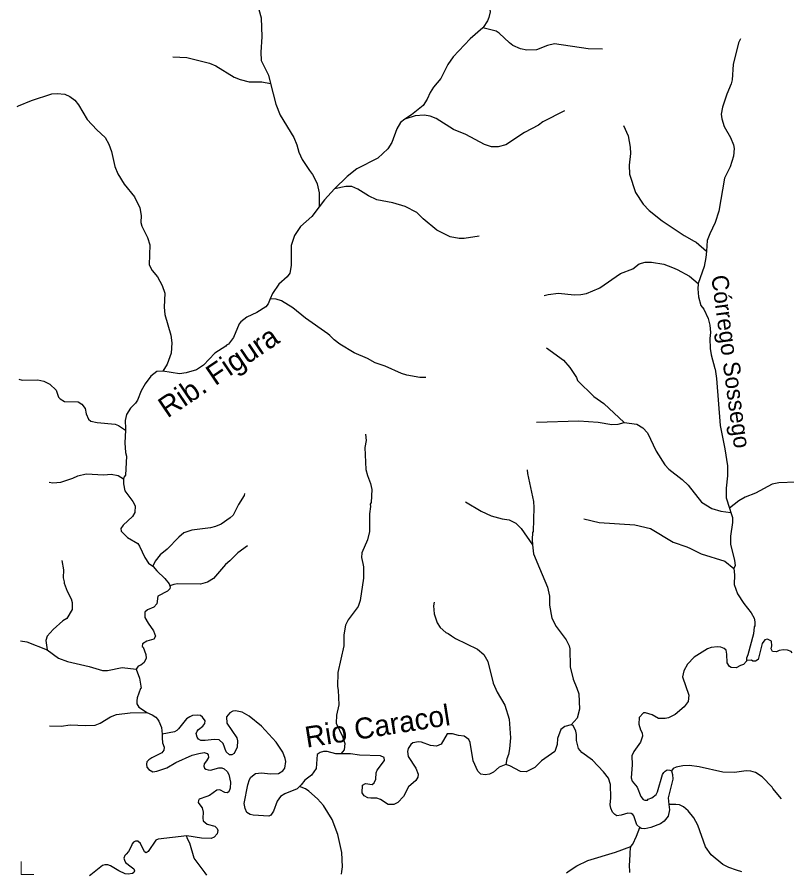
# Model space of a CAD drawing. Extents: x 280.4 to 335.6, y 8893.9 to 8949.5.
# Drawn here: x 280.72 to 288.06, y 8893.92 to 8902.11 of the extents above; entities that cross this region are included whole.
import ezdxf
from ezdxf.enums import TextEntityAlignment as Align

# ---------------------------------------------------------------- set-up
doc = ezdxf.new("R2010")
doc.units = 0
doc.header["$LTSCALE"] = 0.064
doc.linetypes.add('LONG_DASHED', pattern=[7.5, 6, -1.5])
doc.layers.add('61', color=7, linetype='Continuous')
for name, color, linetype, lineweight in [('63', 7, 'Continuous', 13), ('7', 7, 'Continuous', 25), ('9', 7, 'LONG_DASHED', 25)]:
    doc.layers.add(name, color=color, linetype=linetype, lineweight=lineweight)

msp = doc.modelspace()

# ---------------------------------------------------------------- linework, layer by layer
at = {"layer": '63'}
msp.add_lwpolyline([(280.7592, 8894.0583), (280.7592, 8893.9351), (280.8806, 8893.9351)], dxfattribs=at)
at = {"layer": '7'}
msp.add_line((287.5146, 8897.4319), (287.5285, 8897.3884), dxfattribs=at)
for points in [[(285.4001, 8903.403), (285.3942, 8903.3035), (285.3886, 8903.2783), (285.3837, 8903.2596), (285.3395, 8903.1456), (285.2786, 8902.9441), (285.2721, 8902.8349), (285.2848, 8902.7131), (285.2816, 8902.6123), (285.2745, 8902.6053), (285.2499, 8902.5123), (285.2237, 8902.4525), (285.2053, 8902.3693), (285.2336, 8902.1669), (285.2217, 8902.1113), (285.2081, 8902.0799), (285.1646, 8902.0151), (285.1635, 8902.0141)], [(282.7142, 8902.8866), (282.7191, 8902.8812), (282.8616, 8902.669), (282.9288, 8902.5283), (282.9689, 8902.4228), (283.0096, 8902.2445), (283.0488, 8902.1071), (283.0555, 8901.9278), (283.0444, 8901.78), (283.0492, 8901.7026), (283.1196, 8901.561), (283.1389, 8901.4832)], [(285.1635, 8902.0141), (285.0413, 8901.9082), (284.8791, 8901.735), (284.8296, 8901.6631), (284.7614, 8901.5309), (284.6938, 8901.4481), (284.6612, 8901.3953), (284.6327, 8901.3321), (284.5923, 8901.2723), (284.4833, 8901.1815), (284.418, 8901.1425)], [(286.3049, 8901.8106), (286.1668, 8901.8121), (285.8457, 8901.8592), (285.7795, 8901.8454), (285.6734, 8901.8018), (285.5824, 8901.7989), (285.5228, 8901.8139), (285.4491, 8901.8451), (285.4163, 8901.8684), (285.3198, 8901.9635), (285.2912, 8901.9807), (285.1635, 8902.0141)], [(287.6204, 8901.908), (287.6008, 8901.8695), (287.5493, 8901.6634), (287.5399, 8901.5176), (287.5319, 8901.4792), (287.4901, 8901.3802), (287.4487, 8901.2562), (287.4376, 8901.1881), (287.4424, 8901.1449), (287.4647, 8901.0725), (287.5254, 8900.9667), (287.5524, 8900.8971), (287.5589, 8900.8612), (287.5525, 8900.7901), (287.5225, 8900.6861), (287.4677, 8900.579), (287.4133, 8900.2624), (287.3796, 8900.1568), (287.3275, 8900.0491), (287.304, 8899.9846), (287.2957, 8899.8825)], [(282.2074, 8901.7356), (282.3408, 8901.7299), (282.5554, 8901.6767), (282.6179, 8901.6492), (282.7915, 8901.5433), (282.8476, 8901.5186), (282.9347, 8901.4994), (283.0563, 8901.4992), (283.1389, 8901.4832)], [(283.1389, 8901.4832), (283.1883, 8901.2835), (283.2302, 8901.1807), (283.3593, 8900.9667), (283.3881, 8900.8964), (283.4077, 8900.8253), (283.4401, 8900.7572), (283.5083, 8900.6504), (283.5395, 8900.615), (283.5696, 8900.5533), (283.5832, 8900.5253), (283.6024, 8900.439), (283.6014, 8900.3039)], [(280.7217, 8901.2629), (280.7357, 8901.2688), (280.8587, 8901.3203), (281.0536, 8901.383), (281.1033, 8901.3874), (281.1777, 8901.3791), (281.2253, 8901.357), (281.273, 8901.3225), (281.3073, 8901.2774), (281.3896, 8901.139), (281.4813, 8901.0409), (281.562, 8900.9676), (281.5951, 8900.9035), (281.6225, 8900.8324), (281.6532, 8900.691), (281.6805, 8900.6207), (281.7407, 8900.5215), (281.842, 8900.4), (281.8906, 8900.2966), (281.904, 8900.224), (281.9025, 8900.1551), (281.9103, 8900.1199), (281.9655, 8900.012), (281.9855, 8899.9432), (281.981, 8899.7521), (282.0078, 8899.6978), (282.0596, 8899.636), (282.1058, 8899.5554), (282.131, 8899.4801), (282.1248, 8899.3468), (282.1307, 8899.2777), (282.1886, 8899.0803), (282.1982, 8899.0085), (282.1902, 8898.9102), (282.1511, 8898.803), (282.1104, 8898.738)], [(285.9413, 8901.2216), (285.7354, 8901.1178), (285.6953, 8901.085), (285.5592, 8901.0136), (285.3824, 8900.8965), (285.3098, 8900.8773), (285.2471, 8900.8788), (285.18, 8900.901), (285.0001, 8900.9957), (284.8819, 8901.0436), (284.7194, 8901.1486), (284.6618, 8901.1696), (284.6036, 8901.1794), (284.5172, 8901.1745), (284.418, 8901.1425)], [(284.418, 8901.1425), (284.3778, 8901.1085), (284.3433, 8901.0506), (284.2957, 8900.9205), (284.2576, 8900.8591), (284.1612, 8900.7689), (283.9625, 8900.6669), (283.8701, 8900.5962), (283.7483, 8900.4786), (283.7478, 8900.478)], [(286.5054, 8901.0797), (286.5483, 8900.982), (286.5696, 8900.873), (286.5707, 8900.8133), (286.558, 8900.7027), (286.5612, 8900.6172), (286.6194, 8900.4435), (286.6914, 8900.3323), (286.7489, 8900.269), (286.8723, 8900.172), (287.0818, 8900.0317), (287.1798, 8899.9784), (287.1982, 8899.9684), (287.2957, 8899.8825)], [(283.7478, 8900.478), (283.6536, 8900.3718), (283.6014, 8900.3039)], [(285.1265, 8900.0239), (284.9842, 8900.0025), (284.938, 8900.0026), (284.8523, 8900.0177), (284.7251, 8900.0812), (284.5935, 8900.1916), (284.5348, 8900.2503), (284.4218, 8900.3075), (284.3036, 8900.3428), (284.1508, 8900.3714), (284.0727, 8900.4103), (283.971, 8900.4738), (283.9134, 8900.4979), (283.8552, 8900.4997), (283.7478, 8900.478)], [(283.6014, 8900.3039), (283.5316, 8900.213), (283.424, 8900.1178), (283.3661, 8900.0303), (283.3344, 8899.9365), (283.3353, 8899.7449), (283.321, 8899.6721), (283.2969, 8899.6378), (283.2174, 8899.5677), (283.1582, 8899.4769), (283.1361, 8899.4265)], [(287.2957, 8899.8825), (287.2907, 8899.8216), (287.2743, 8899.7354), (287.2172, 8899.5736)], [(285.7466, 8899.4581), (285.7853, 8899.4702), (285.8849, 8899.4825), (286.0351, 8899.4667), (286.0981, 8899.4676), (286.1516, 8899.4795), (286.2726, 8899.5295), (286.2802, 8899.5326), (286.4759, 8899.6701), (286.5933, 8899.7146), (286.6555, 8899.7609), (286.7121, 8899.7769), (286.7706, 8899.7768), (286.8905, 8899.7576), (286.9717, 8899.7263), (287.0169, 8899.7088), (287.135, 8899.6448), (287.2172, 8899.5736)], [(287.2172, 8899.5736), (287.2159, 8899.57), (287.2124, 8899.5235), (287.2183, 8899.4467), (287.2418, 8899.3628), (287.2704, 8899.33), (287.311, 8899.2395), (287.3271, 8899.1756), (287.3352, 8899.1067), (287.3288, 8899.0493), (287.3306, 8898.9533), (287.3412, 8898.8925), (287.3767, 8898.763), (287.3778, 8898.7564), (287.3926, 8898.667), (287.4279, 8898.22), (287.4725, 8897.996), (287.495, 8897.8347), (287.495, 8897.7394), (287.4823, 8897.6218), (287.4839, 8897.5284), (287.5146, 8897.4319)], [(283.1361, 8899.4265), (283.1154, 8899.3792), (283.0929, 8899.3505), (283.0082, 8899.2975), (282.9109, 8899.2518), (282.8562, 8899.2092), (282.8404, 8899.1879), (282.7835, 8899.0573), (282.7381, 8898.9946), (282.7167, 8898.9865), (282.7109, 8898.9755), (282.6075, 8898.9102), (282.4994, 8898.7956), (282.4313, 8898.7518), (282.3326, 8898.7215), (282.2703, 8898.7136), (282.1104, 8898.738)], [(284.6181, 8898.6768), (284.5625, 8898.6783), (284.4373, 8898.6991), (284.3887, 8898.7138), (284.2299, 8898.7866), (284.1347, 8898.8184), (284.0626, 8898.8584), (283.936, 8898.9112), (283.7992, 8898.9952), (283.7461, 8899.0354), (283.7028, 8899.0773), (283.6856, 8899.094), (283.4727, 8899.2441), (283.3518, 8899.3431), (283.2442, 8899.409), (283.1921, 8899.4248), (283.1361, 8899.4265)], [(285.7712, 8898.9599), (285.9314, 8898.8425), (285.9917, 8898.7725), (286.0557, 8898.6766), (286.0643, 8898.6488), (286.2221, 8898.4945), (286.3185, 8898.4281), (286.5102, 8898.2477)], [(282.1104, 8898.738), (282.055, 8898.7334), (281.9956, 8898.6906), (281.9419, 8898.6173), (281.9044, 8898.5494), (281.87, 8898.4617), (281.8507, 8898.433)], [(280.7373, 8898.6615), (280.7684, 8898.6515), (280.9182, 8898.6558), (280.9771, 8898.6427), (281.034, 8898.6126), (281.0942, 8898.5554), (281.1157, 8898.4906), (281.1315, 8898.4732), (281.1724, 8898.4496), (281.3036, 8898.4464), (281.3394, 8898.4222), (281.3698, 8898.38), (281.3799, 8898.3305), (281.4021, 8898.2794), (281.4238, 8898.2613), (281.4835, 8898.2467), (281.657, 8898.2305), (281.6865, 8898.2207), (281.7543, 8898.1759)], [(281.8507, 8898.433), (281.8013, 8898.3849), (281.7636, 8898.3253), (281.7507, 8898.2679), (281.7552, 8898.1917), (281.7543, 8898.1759)], [(285.6761, 8898.2523), (286.0773, 8898.264), (286.2636, 8898.2512), (286.3923, 8898.2289), (286.453, 8898.2307), (286.5102, 8898.2477)], [(286.5102, 8898.2477), (286.6307, 8898.2305), (286.6905, 8898.197), (286.7339, 8898.1496), (286.8166, 8897.9736), (286.8986, 8897.8435), (286.9368, 8897.8027), (287.0642, 8897.7047), (287.1224, 8897.6499), (287.2477, 8897.488), (287.3473, 8897.4282), (287.3486, 8897.4274), (287.4343, 8897.4005), (287.5285, 8897.3884)], [(281.7543, 8898.1759), (281.7475, 8898.0546), (281.7539, 8897.9602), (281.7633, 8897.9274), (281.7536, 8897.7461), (281.7409, 8897.7305), (281.7349, 8897.7093)], [(284.0444, 8898.1367), (284.0489, 8898.0759), (284.0377, 8898.0091), (284.0471, 8897.8009), (284.0615, 8897.7435), (284.092, 8897.6653), (284.1046, 8897.6076), (284.0981, 8897.4855), (284.0892, 8897.4676), (284.0918, 8897.446), (284.0823, 8897.378), (284.0806, 8897.2092), (284.063, 8897.1286), (284.0083, 8897.0043), (284.0069, 8896.9605), (284.0179, 8896.904), (284.0246, 8896.8694), (284.0261, 8896.7639), (283.9941, 8896.5497), (283.9731, 8896.4915), (283.878, 8896.3646), (283.8535, 8896.3156), (283.836, 8896.2209), (283.8386, 8896.118), (283.7785, 8895.8626), (283.7753, 8895.7277), (283.7832, 8895.6939), (283.7911, 8895.5556), (283.7657, 8895.4557), (283.7625, 8895.3787), (283.8238, 8895.2526), (283.8454, 8895.1838), (283.8389, 8895.1248), (283.8073, 8895.0874)], [(288.541, 8898.1756), (288.4966, 8898.0414), (288.4129, 8897.8643), (288.3765, 8897.8128), (288.3176, 8897.7531), (288.2442, 8897.711), (288.1491, 8897.6791), (287.9876, 8897.6723), (287.923, 8897.6592), (287.7644, 8897.5751), (287.6662, 8897.5355), (287.6053, 8897.502), (287.5146, 8897.4319)], [(285.5854, 8897.7958), (285.5874, 8897.7628), (285.6446, 8897.4931), (285.6494, 8897.4363), (285.6432, 8897.2064), (285.6379, 8897.198), (285.6323, 8897.1315), (285.6368, 8897.0814)], [(281.0276, 8897.6784), (281.062, 8897.671), (281.139, 8897.6801), (281.2521, 8897.7157), (281.3016, 8897.7385), (281.3804, 8897.757), (281.5473, 8897.7491), (281.6177, 8897.7551), (281.6833, 8897.7409), (281.7349, 8897.7093)], [(281.7349, 8897.7093), (281.7348, 8897.6638), (281.7474, 8897.5965), (281.8256, 8897.4947), (281.8478, 8897.4516), (281.8447, 8897.3878), (281.8224, 8897.3524), (281.7331, 8897.2675), (281.7096, 8897.2357), (281.712, 8897.2117), (281.7724, 8897.1499), (281.873, 8897.0919), (281.8899, 8897.0686), (281.9377, 8896.9591), (281.9728, 8896.9052), (282.0147, 8896.8762)], [(282.8886, 8897.5713), (282.8863, 8897.5516), (282.8313, 8897.467), (282.7815, 8897.3647), (282.7526, 8897.3368), (282.6687, 8897.2777), (282.6147, 8897.254), (282.5646, 8897.2419), (282.3871, 8897.2197), (282.3106, 8897.1949), (282.2633, 8897.1551), (282.1524, 8897.0394), (282.0859, 8896.9857), (282.0384, 8896.9238), (282.0147, 8896.8762)], [(284.9973, 8897.4917), (285.1477, 8897.4003), (285.2427, 8897.357), (285.3481, 8897.3287), (285.4144, 8897.3183), (285.4762, 8897.2888), (285.5279, 8897.2357), (285.6368, 8897.0814)], [(287.5285, 8897.3884), (287.543, 8897.3428), (287.543, 8897.2923), (287.524, 8897.1644), (287.5239, 8897.0877), (287.5639, 8896.9319), (287.5684, 8896.883), (287.5562, 8896.8554)], [(286.1248, 8897.3293), (286.2739, 8897.2948), (286.6131, 8897.2726), (286.7626, 8897.2357), (286.9798, 8897.1072), (287.1096, 8897.0613), (287.1429, 8897.0448), (287.2459, 8896.9935), (287.4709, 8896.9246), (287.5562, 8896.8554)], [(282.9175, 8897.0713), (282.8247, 8897.0034), (282.7505, 8896.9276), (282.708, 8896.8929), (282.5934, 8896.7608), (282.5357, 8896.7257), (282.4694, 8896.7051), (282.2497, 8896.7083), (282.2151, 8896.7032), (282.1775, 8896.688)], [(285.6368, 8897.0814), (285.6447, 8896.9948), (285.7027, 8896.8593), (285.7803, 8896.6782), (285.7982, 8896.5912), (285.7983, 8896.5056), (285.8226, 8896.3803), (285.8611, 8896.3027), (285.9581, 8896.1753), (285.985, 8896.1185), (285.9917, 8896.0883), (285.995, 8895.9171), (286.0231, 8895.7984), (286.0608, 8895.7141), (286.0778, 8895.6588), (286.0845, 8895.5141), (286.0619, 8895.427), (286.0065, 8895.3629)], [(282.0147, 8896.8762), (282.0193, 8896.873), (282.0522, 8896.8331), (282.1295, 8896.7591), (282.1717, 8896.7085), (282.1775, 8896.688)], [(287.5562, 8896.8554), (287.5621, 8896.7957), (287.5609, 8896.7025), (287.5917, 8896.6126), (287.6513, 8896.5215), (287.7221, 8896.4319), (287.7497, 8896.3796), (287.7573, 8896.3473), (287.7573, 8896.3094), (287.751, 8896.299), (287.7444, 8896.2322), (287.6898, 8896.0308), (287.6765, 8895.9996), (287.6764, 8895.9703)], [(282.1775, 8896.688), (282.1801, 8896.6789), (282.1779, 8896.6602), (282.1554, 8896.6392), (282.0639, 8896.5904), (282.0544, 8896.5183), (282.0265, 8896.4865), (281.9649, 8896.4615), (281.9377, 8896.4368), (281.9394, 8896.3888), (281.9703, 8896.3337), (282.0224, 8896.2617), (282.0397, 8896.2106), (282.0248, 8896.18), (281.9592, 8896.1611), (281.9156, 8896.135), (281.914, 8896.1101), (281.9218, 8896.1035), (281.9485, 8896.0353), (281.9516, 8895.999), (281.9338, 8895.9576), (281.9012, 8895.9329), (281.877, 8895.9241), (281.8551, 8895.8945)], [(284.6974, 8896.5339), (284.6933, 8896.4995), (284.7002, 8896.4224), (284.7269, 8896.3353), (284.7545, 8896.2916), (284.8088, 8896.2441), (284.8316, 8896.2355), (284.8651, 8896.2119), (284.9011, 8896.1866), (285.1111, 8896.0854), (285.1732, 8896.0339), (285.211, 8895.9681), (285.2629, 8895.7625), (285.2996, 8895.6759), (285.3728, 8895.5516), (285.4126, 8895.418), (285.4256, 8895.2382), (285.4174, 8895.1344), (285.4068, 8895.0797), (285.3904, 8895.0375), (285.3838, 8894.9843)], [(288.1132, 8896.0501), (288.1045, 8896.063), (288.0677, 8896.0768), (288.0305, 8896.0797), (287.9877, 8896.0733), (287.9641, 8896.0587), (287.9245, 8896.0635), (287.9128, 8896.089), (287.9188, 8896.118), (287.9169, 8896.1608), (287.8773, 8896.1796), (287.8534, 8896.1738), (287.8286, 8896.1385), (287.7874, 8895.9854), (287.7644, 8895.9708), (287.7367, 8895.9722), (287.7246, 8895.9817), (287.6819, 8895.9764), (287.6764, 8895.9703)], [(287.6764, 8895.9703), (287.6492, 8895.9404), (287.6192, 8895.9309), (287.5807, 8895.9084), (287.5326, 8895.909), (287.5147, 8895.9209), (287.4921, 8895.9536), (287.4915, 8896.0383), (287.4822, 8896.0756), (287.4641, 8896.0912), (287.4337, 8896.1034), (287.4016, 8896.1066), (287.34, 8896.1005), (287.3057, 8896.0886), (287.1797, 8896.0074), (287.1161, 8895.9419), (287.0793, 8895.8779), (287.0684, 8895.8206), (287.1271, 8895.6469), (287.1214, 8895.5863), (287.0835, 8895.5351), (286.9961, 8895.4622), (286.9337, 8895.4308), (286.903, 8895.4228), (286.8369, 8895.4253), (286.7786, 8895.4573)], [(281.8551, 8895.8945), (281.8884, 8895.808), (281.9038, 8895.7125), (281.8977, 8895.7091), (281.8672, 8895.6213), (281.8625, 8895.5932), (281.8626, 8895.5653), (281.882, 8895.5327), (281.9559, 8895.4833), (281.9575, 8895.4826)], [(281.0308, 8895.3553), (281.1428, 8895.3518), (281.227, 8895.3646), (281.3742, 8895.3565), (281.4645, 8895.3612), (281.5126, 8895.3783), (281.6109, 8895.4411), (281.6687, 8895.4608), (281.8002, 8895.4764), (281.9575, 8895.4826)], [(281.9575, 8895.4826), (282.0096, 8895.4603), (282.0438, 8895.4374), (282.0614, 8895.4189), (282.074, 8895.3982), (282.099, 8895.3373), (282.1055, 8895.2733)], [(283.4141, 8894.7752), (283.3921, 8894.7543), (283.2731, 8894.7039), (283.2347, 8894.6783), (283.2024, 8894.6362), (283.1658, 8894.541), (283.1416, 8894.5012), (283.1228, 8894.4913), (282.9724, 8894.501), (282.9443, 8894.5088), (282.9134, 8894.5286), (282.8957, 8894.5642), (282.8881, 8894.6118), (282.9217, 8894.79), (282.9382, 8894.8432), (282.9515, 8894.8638), (282.9946, 8894.8977), (283.053, 8894.904), (283.1379, 8894.8944), (283.2134, 8894.8988), (283.2547, 8894.9243), (283.2744, 8894.9498), (283.2825, 8895.0143), (283.2775, 8895.0438), (283.2539, 8895.1032), (283.1914, 8895.1966), (283.0523, 8895.3517), (282.9349, 8895.4449), (282.866, 8895.4847), (282.8053, 8895.4972), (282.7773, 8895.494), (282.7495, 8895.4788), (282.7181, 8895.4383), (282.7198, 8895.3781), (282.8157, 8895.2408), (282.822, 8895.2094), (282.8188, 8895.1518), (282.7924, 8895.0899), (282.7676, 8895.077), (282.7456, 8895.0771), (282.7163, 8895.1045), (282.6858, 8895.1869), (282.6486, 8895.2206), (282.5997, 8895.2238), (282.5133, 8895.2127), (282.4732, 8895.2143), (282.4523, 8895.2262), (282.4393, 8895.2463), (282.4292, 8895.2804), (282.4376, 8895.302), (282.4499, 8895.3179), (282.4925, 8895.3518), (282.5128, 8895.3768), (282.5147, 8895.4013), (282.4908, 8895.436), (282.4701, 8895.4523), (282.4386, 8895.4572), (282.3942, 8895.4515), (282.37, 8895.4394), (282.3363, 8895.4219), (282.2593, 8895.3246), (282.2452, 8895.3083), (282.2224, 8895.2979), (282.1055, 8895.2733)], [(286.7786, 8895.4573), (286.714, 8895.4781), (286.6962, 8895.478), (286.6539, 8895.4325), (286.6512, 8895.3698), (286.6664, 8895.3156), (286.6824, 8895.2862), (286.6856, 8895.2564), (286.6678, 8895.1992), (286.6031, 8895.1093), (286.5826, 8895.0689), (286.5881, 8894.9816), (286.5773, 8894.8577), (286.5887, 8894.8272), (286.6361, 8894.7683), (286.67, 8894.6785), (286.6912, 8894.6526), (286.7066, 8894.6434), (286.732, 8894.6436), (286.7406, 8894.6527), (286.775, 8894.6659), (286.8156, 8894.6998), (286.8297, 8894.7255), (286.8778, 8894.8882), (286.8884, 8894.9072), (286.9029, 8894.9206), (286.9222, 8894.9327), (286.9472, 8894.932), (286.9626, 8894.9258)], [(286.0065, 8895.3629), (285.9463, 8895.348), (285.9069, 8895.3189), (285.8754, 8895.2332), (285.8718, 8895.1743), (285.8489, 8895.11), (285.724, 8895.0213), (285.6591, 8894.9552), (285.5769, 8894.9136), (285.5232, 8894.919), (285.4215, 8894.9723), (285.3838, 8894.9843)], [(286.6612, 8894.3854), (286.6329, 8894.4106), (286.6035, 8894.4957), (286.5927, 8894.5079), (286.5784, 8894.5182), (286.5467, 8894.5214), (286.4836, 8894.5009), (286.4418, 8894.4962), (286.4204, 8894.5075), (286.4006, 8894.5301), (286.3822, 8894.5692), (286.3774, 8894.6001), (286.3835, 8894.6656), (286.3819, 8894.7929), (286.3608, 8894.8549), (286.3153, 8894.9162), (286.2076, 8895.0271), (286.1076, 8895.0986), (286.0739, 8895.1387), (286.0576, 8895.2143), (286.0573, 8895.2727), (286.0506, 8895.3029), (286.0231, 8895.3555), (286.0065, 8895.3629)], [(282.1055, 8895.2733), (282.1045, 8895.2397), (282.1087, 8895.1926), (282.1245, 8895.1518), (282.1209, 8895.1222), (282.1025, 8895.0964), (282.0071, 8895.0499), (281.9784, 8895.0292), (281.9589, 8895.009), (281.9542, 8894.9871), (281.9597, 8894.9592), (281.9784, 8894.9359), (282.0162, 8894.9155), (282.0548, 8894.9225), (282.1477, 8894.9539)], [(285.3838, 8894.9843), (285.3188, 8894.9595), (285.2632, 8894.9108), (285.2272, 8894.8912), (285.185, 8894.8864), (285.1453, 8894.8917), (285.1144, 8894.9218), (285.0708, 8895.02), (285.0434, 8895.1933), (285.0289, 8895.2223), (284.9857, 8895.2556), (284.9314, 8895.262), (284.8738, 8895.2779), (284.8214, 8895.2778), (284.7665, 8895.1779), (284.7212, 8895.16), (284.6636, 8895.1664), (284.5764, 8895.1984), (284.5485, 8895.2013), (284.4949, 8895.1916), (284.4747, 8895.1759), (284.4521, 8895.1365), (284.4456, 8895.1077), (284.4502, 8895.06), (284.5243, 8894.9488), (284.5455, 8894.8943), (284.5441, 8894.8641), (284.5242, 8894.8331), (284.4549, 8894.7728), (284.4057, 8894.6791)], [(282.1477, 8894.9539), (282.2342, 8895.005), (282.3903, 8895.0735), (282.455, 8895.0911), (282.505, 8895.0992), (282.5324, 8895.0907), (282.5417, 8895.0774), (282.5453, 8895.0516), (282.5277, 8895.021), (282.5054, 8894.9905), (282.5011, 8894.9681), (282.5079, 8894.9514), (282.522, 8894.9415), (282.5427, 8894.9332), (282.5655, 8894.9313), (282.6454, 8894.9533), (282.6725, 8894.9534), (282.6966, 8894.9431), (282.7255, 8894.9167), (282.7404, 8894.8906), (282.7547, 8894.8167), (282.7545, 8894.7578), (282.7395, 8894.7227), (282.726, 8894.716), (282.7032, 8894.7169), (282.6543, 8894.742), (282.6271, 8894.7392), (282.5547, 8894.6904), (282.5303, 8894.6787), (282.4586, 8894.6546), (282.4511, 8894.6419), (282.4493, 8894.6226), (282.4639, 8894.5987), (282.487, 8894.5706), (282.4956, 8894.5313), (282.491, 8894.4722), (282.4961, 8894.4468), (282.5336, 8894.4152), (282.6063, 8894.3958), (282.6297, 8894.376), (282.6366, 8894.3559), (282.6287, 8894.3244), (282.6015, 8894.2919), (282.5709, 8894.2802), (282.4796, 8894.2825), (282.3401, 8894.3048)], [(283.8073, 8895.0874), (283.7608, 8895.0881), (283.6789, 8895.1081), (283.6424, 8895.1081), (283.6115, 8895.0985), (283.5818, 8895.0791), (283.5737, 8894.9479), (283.5279, 8894.8841), (283.4653, 8894.8354), (283.4301, 8894.7904), (283.4141, 8894.7752)], [(284.4057, 8894.6791), (284.3535, 8894.6238), (284.314, 8894.603), (284.2591, 8894.6044), (284.1862, 8894.6512), (284.1533, 8894.6652), (284.095, 8894.6625), (284.0663, 8894.6674), (284.0309, 8894.6854), (284.0121, 8894.7132), (284.0156, 8894.7873), (284.0446, 8894.8046), (284.1077, 8894.7957), (284.1268, 8894.8115), (284.1414, 8894.8456), (284.1464, 8894.9055), (284.1564, 8894.9316), (284.224, 8895.0233), (284.2224, 8895.0511), (284.1862, 8895.0688), (283.9856, 8895.0736), (283.9006, 8895.0861), (283.8073, 8895.0874)], [(286.9626, 8894.9258), (286.9713, 8894.8909), (286.9737, 8894.846), (286.9307, 8894.6664), (286.937, 8894.602)], [(288.0113, 8894.6587), (287.9283, 8894.756), (287.9231, 8894.7699), (287.8283, 8894.8683), (287.7651, 8894.908), (287.7196, 8894.9213), (287.6748, 8894.9231), (287.5622, 8894.9088), (287.4527, 8894.9117), (287.2271, 8894.963), (287.1354, 8894.9758), (287.0703, 8894.9728), (287.0076, 8894.9594), (286.9797, 8894.9459), (286.9626, 8894.9258)], [(283.8163, 8893.9374), (283.8193, 8893.9631), (283.8248, 8894.0096), (283.8196, 8894.1459), (283.7813, 8894.3177), (283.7269, 8894.4616), (283.6426, 8894.5948), (283.5875, 8894.6565), (283.5039, 8894.7308), (283.4712, 8894.752), (283.4141, 8894.7752)], [(286.937, 8894.602), (286.9417, 8894.5535), (286.9319, 8894.493), (286.891, 8894.4455), (286.8569, 8894.4196), (286.7642, 8894.3824), (286.7082, 8894.3716), (286.6741, 8894.3739), (286.6612, 8894.3854)], [(287.6319, 8893.96), (287.583, 8893.9765), (287.5095, 8894.0013), (287.4517, 8894.0315), (287.3393, 8894.1232), (287.2875, 8894.1984), (287.2136, 8894.4066), (287.1751, 8894.4769), (287.1224, 8894.5441), (287.0776, 8894.5824), (287.0376, 8894.6), (287.0033, 8894.6048), (286.937, 8894.602)], [(286.5749, 8894.2041), (286.5923, 8894.2246), (286.6294, 8894.3004), (286.6612, 8894.3854)], [(282.3401, 8894.3048), (282.0679, 8894.2739), (282.0443, 8894.2636), (281.9722, 8894.1557), (281.952, 8894.1432), (281.9357, 8894.1506), (281.8968, 8894.2303), (281.8731, 8894.2521), (281.8505, 8894.2534), (281.8306, 8894.2428), (281.8173, 8894.2268), (281.8109, 8894.2077), (281.7834, 8894.1556), (281.7598, 8894.1287), (281.747, 8894.1181), (281.7391, 8894.0929), (281.7459, 8894.0716), (281.7548, 8894.0492), (281.8101, 8894.0076), (281.8333, 8893.9894), (281.8412, 8893.9721), (281.8343, 8893.9555), (281.8213, 8893.9456), (281.7815, 8893.9376), (281.7528, 8893.9428), (281.6898, 8893.9701), (281.6129, 8894.0194), (281.5852, 8894.0292), (281.5593, 8894.0275), (281.5356, 8894.0222), (281.4227, 8893.9317), (281.4118, 8893.9229)], [(282.532, 8893.9297), (282.5147, 8893.9523), (282.4096, 8894.09), (282.3696, 8894.233), (282.3443, 8894.2811), (282.3401, 8894.3048)], [(285.9599, 8893.9501), (285.9871, 8893.9692), (286.0589, 8894.0195), (286.1635, 8894.0677), (286.4298, 8894.1485), (286.5749, 8894.2041)], [(286.5648, 8893.9537), (286.5635, 8893.9777), (286.5619, 8894.0076), (286.5644, 8894.0804), (286.5676, 8894.1156), (286.5676, 8894.1508), (286.5749, 8894.2041)]]:
    msp.add_lwpolyline(points, dxfattribs=at)
at = {"layer": '9'}
for points in [[(281.1483, 8896.9306), (281.1625, 8896.8407), (281.161, 8896.767), (281.1713, 8896.7279), (281.1689, 8896.714), (281.1989, 8896.639), (281.237, 8896.5656), (281.2451, 8896.5297), (281.245, 8896.4624), (281.1942, 8896.3792), (281.1565, 8896.3547), (281.0655, 8896.2742), (281.0062, 8896.2096), (280.9943, 8896.1681), (281.0067, 8896.0801)], [(280.7524, 8896.166), (280.8146, 8896.1553), (281.0067, 8896.0801)], [(281.0067, 8896.0801), (281.1174, 8895.9979), (281.2028, 8895.9669), (281.4092, 8895.9213), (281.5344, 8895.8817), (281.5835, 8895.8813), (281.7217, 8895.9115), (281.8551, 8895.8945)]]:
    msp.add_lwpolyline(points, dxfattribs=at)

# ---------------------------------------------------------------- texts
at = {"layer": '61'}
for s, height, rotation, p in [('Córrego Sossego', 0.16, 277.595, (287.451, 8898.819)), ('Rib. Figura', 0.2, 34.077, (282.6967, 8898.6508)), ('Rio Caracol', 0.2, 8.973, (284.173, 8895.2537))]:
    msp.add_text(s, height=height, rotation=rotation, dxfattribs=at).set_placement(p, align=Align.CENTER)

doc.saveas('drawing.dxf')
